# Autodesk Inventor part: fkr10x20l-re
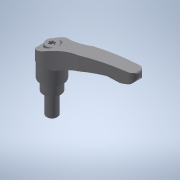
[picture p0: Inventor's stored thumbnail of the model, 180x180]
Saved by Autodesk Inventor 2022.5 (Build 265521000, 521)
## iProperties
Created: 2017-09
Part Number: fkr10x20l-re
Material: 一般
Document SubType Name: Modeling
Designer: imaocorp
Density: 1 g/cm^3
Appearance: 既定
Author: imaocorp
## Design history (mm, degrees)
node "fkr10x20l-re.x_t1"
node "fkr10x20l-re"
node "Base1"
